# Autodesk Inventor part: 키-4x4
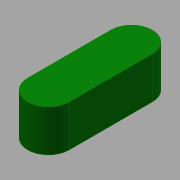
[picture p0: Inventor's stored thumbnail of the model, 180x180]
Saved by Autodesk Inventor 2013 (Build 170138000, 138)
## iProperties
Created: 2015-12
Part Number: 키-4x4
Document SubType Name: Modeling
Designer: mdu
Density: 7.86 g/cm^3
Material: 강철, 연강
Mass: 1.40117 g
Surface Area: 2.03398 cm^2
Volume: 0.178265 cm^3
Author: mdu
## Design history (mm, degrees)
sketch "스케치1"
  geometry: L1 (-2, -10)-(-2, -2) reference; L2 (2, -2)-(2, -10) reference; A1 r 2 centre (0, -2) between (2, -2) and (-2, -2) reference; A2 r 2 centre (0, -10) between (-2, -10) and (2, -10) reference; 1 further point
extrude "돌출1" new body sketch "스케치1" distance "d0" = 4; taper "d1" = 0 deg
node "솔리드1"
node "참조1"
